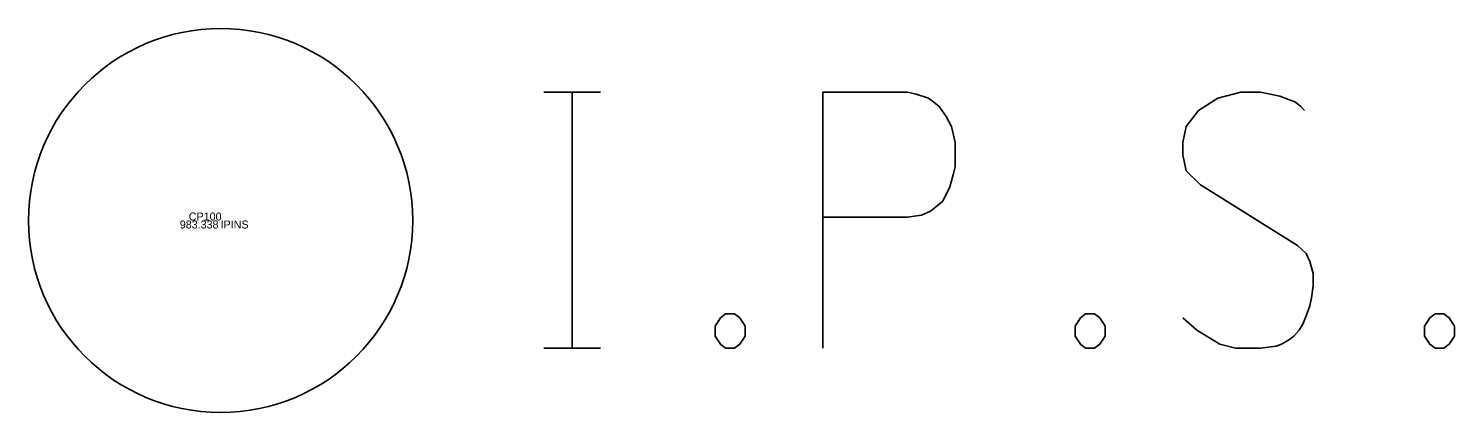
# Model space of a CAD drawing. Extents: x 215723 to 216239, y 335392 to 336474.
# Drawn here: x 216128.67 to 216137.58, y 335391.77 to 335394.17 of the extents above; entities that cross this region are included whole.
import ezdxf

# ---------------------------------------------------------------- set-up
doc = ezdxf.new("R2010")
doc.units = 0
for name, color, linetype in [('DV_X_Property_Line', 7, 'Continuous'), ('RW_X_Esmt_SH', 7, 'Continuous'), ('RW_X_Fee_RW', 7, 'Continuous'), ('SV_P_Mon_Cells_Set', 7, 'Continuous')]:
    doc.layers.add(name, color=color, linetype=linetype)

msp = doc.modelspace()

# ---------------------------------------------------------------- linework, layer by layer
at = {"layer": 'SV_P_Mon_Cells_Set'}
for points in [[(216131.8937, 335393.7751), (216132.2464, 335393.7751)], [(216132.07, 335392.1751), (216132.07, 335393.7751)], [(216133.6353, 335392.1751), (216133.6353, 335393.7751), (216134.1644, 335393.7751), (216134.2196, 335393.7624), (216134.2967, 335393.7372), (216134.3298, 335393.712), (216134.3628, 335393.6868), (216134.4069, 335393.6239), (216134.4401, 335393.5608), (216134.4621, 335393.46), (216134.4621, 335393.3089), (216134.451, 335393.2585), (216134.429, 335393.1829), (216134.3849, 335393.0948), (216134.3408, 335393.0569), (216134.3078, 335393.0317), (216134.2526, 335393.0065), (216134.1644, 335392.994), (216133.6353, 335392.994)], [(216136.6447, 335393.6616), (216136.6226, 335393.6868), (216136.5895, 335393.712), (216136.4903, 335393.7499), (216136.369, 335393.7751), (216136.2808, 335393.7751), (216136.2478, 335393.7751), (216136.1044, 335393.7372), (216135.9833, 335393.6616), (216135.906, 335393.5608), (216135.884, 335393.46), (216135.884, 335393.3844), (216135.906, 335393.2837), (216135.9942, 335393.1956), (216136.6006, 335392.8176), (216136.6556, 335392.7673), (216136.6776, 335392.7169), (216136.6997, 335392.6413), (216136.6997, 335392.5657), (216136.6887, 335392.4901), (216136.6776, 335392.4397), (216136.6556, 335392.3766), (216136.6335, 335392.3262), (216136.6115, 335392.2885), (216136.5785, 335392.2507), (216136.5454, 335392.2255), (216136.5013, 335392.2003), (216136.4683, 335392.1878), (216136.369, 335392.1751), (216136.2147, 335392.1751), (216136.1156, 335392.2003), (216135.9722, 335392.2885), (216135.884, 335392.3641)], [(216133.0291, 335392.3893), (216133.0842, 335392.3893), (216133.1173, 335392.3641), (216133.1503, 335392.3137), (216133.1503, 335392.2507), (216133.1173, 335392.2003), (216133.0842, 335392.1751), (216133.0291, 335392.1751), (216132.996, 335392.2003), (216132.963, 335392.2507), (216132.963, 335392.3137), (216132.996, 335392.3641), (216133.0291, 335392.3893)], [(216135.2778, 335392.3893), (216135.3328, 335392.3893), (216135.366, 335392.3641), (216135.399, 335392.3137), (216135.399, 335392.2507), (216135.366, 335392.2003), (216135.3328, 335392.1751), (216135.2778, 335392.1751), (216135.2447, 335392.2003), (216135.2117, 335392.2507), (216135.2117, 335392.3137), (216135.2447, 335392.3641), (216135.2778, 335392.3893)], [(216137.4604, 335392.3893), (216137.5154, 335392.3893), (216137.5485, 335392.3641), (216137.5815, 335392.3137), (216137.5815, 335392.2507), (216137.5485, 335392.2003), (216137.5154, 335392.1751), (216137.4604, 335392.1751), (216137.4272, 335392.2003), (216137.3942, 335392.2507), (216137.3942, 335392.3137), (216137.4272, 335392.3641), (216137.4604, 335392.3893)], [(216131.8937, 335392.1751), (216132.2464, 335392.1751)]]:
    msp.add_lwpolyline(points, dxfattribs=at)
msp.add_circle((216129.8747, 335392.9734), 1.2, dxfattribs=at)

# ---------------------------------------------------------------- texts
at = {"layer": 'DV_X_Property_Line'}
msp.add_text('983.338', height=0.05, dxfattribs=at).set_placement((216129.6197, 335392.9234))
at = {"layer": 'RW_X_Esmt_SH'}
msp.add_text('IPINS', height=0.05, dxfattribs=at).set_placement((216129.8747, 335392.9234))
at = {"layer": 'RW_X_Fee_RW'}
msp.add_text('CP100', height=0.05, dxfattribs=at).set_placement((216129.6758, 335392.9734))

doc.saveas('drawing.dxf')
